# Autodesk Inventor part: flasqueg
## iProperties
Shininess: 21.0
Length Units: 11269
Angle Units: 11279
Time Units: 11290
Mass Units: 11283
Length Display Precision: 3
Angle Display Precision: 2
Compacted: True
Created: 2001-12
Part Number: flasqueg
Material: Par défaut
Document SubType Name: Modélisation
Designer: pichon
Density: 0.0
Volumn: 0.0
Area: 0.0
PropertySet Name: Model Information
Control State: 0
Master: False
Checked Out: False
Author: pichon
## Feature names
1. Corps dérivé1 [Tagging]
